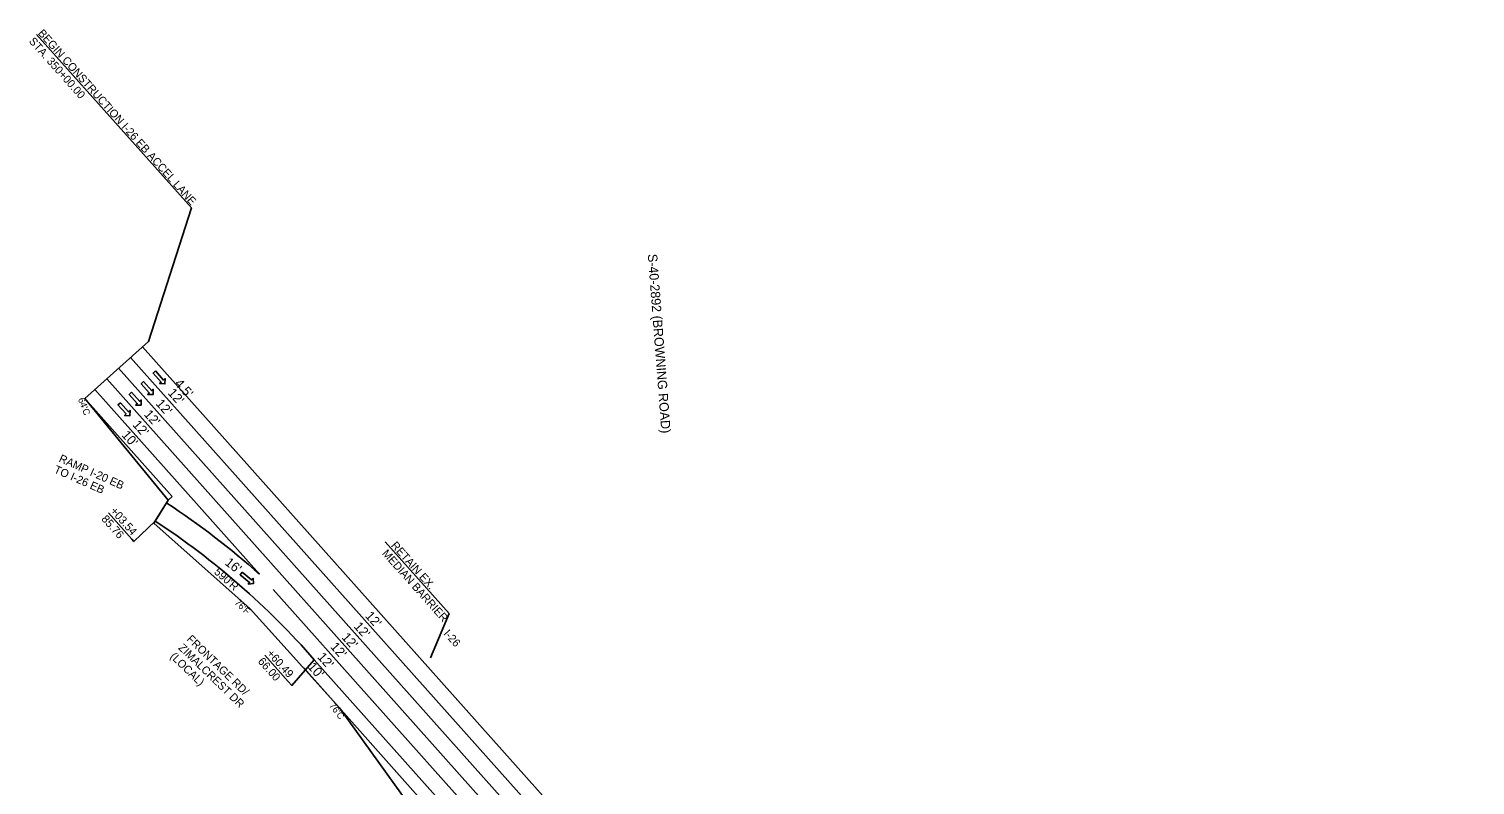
# Model space of a CAD drawing. Extents: x 1966090 to 1975830, y 788086 to 801233.
# Drawn here: x 1967014 to 1968098, y 800666 to 801233 of the extents above; entities that cross this region are included whole.
import ezdxf

# ---------------------------------------------------------------- set-up
doc = ezdxf.new("R2010")
doc.units = 0
for name, color, linetype in [('BR_PROPOSED_DRAINAGE', 7, 'Continuous'), ('RD_EX_Driveway_txCode', 7, 'Continuous'), ('RD_EX_RW_TX', 7, 'Continuous'), ('RD_EX_SU_Gas', 7, 'Continuous'), ('RD_EX_SU_H2O', 7, 'Continuous'), ('RD_PD_PaveShd', 7, 'Continuous'), ('RD_Sketch6', 7, 'Continuous'), ('RD_Sketch8', 7, 'Continuous')]:
    doc.layers.add(name, color=color, linetype=linetype)

msp = doc.modelspace()

# ---------------------------------------------------------------- linework, layer by layer
at = {"layer": 'BR_PROPOSED_DRAINAGE'}
for p, q in [((1967107.2, 800862.5), (1967179.5, 800798.4)), ((1967179.5, 800798.4), (1967246.3, 800724.1)), ((1967246.3, 800724.1), (1967305, 800642.4))]:
    msp.add_line(p, q, dxfattribs=at)
msp.add_lwpolyline([(1967055.5, 800955.8), (1967118, 800879.8), (1967107.2, 800862.5)], dxfattribs=at)
at = {"layer": 'RD_EX_Driveway_txCode'}
for points in [[(1967108.4, 800976.5), (1967106.6, 800974.9), (1967112.7, 800968.1), (1967111.5, 800967), (1967115.5, 800966.8), (1967115.8, 800970.8), (1967114.5, 800969.7)], [(1967099.5, 800968.5), (1967097.7, 800966.9), (1967103.8, 800960.1), (1967102.6, 800959), (1967106.6, 800958.8), (1967106.8, 800962.8), (1967105.6, 800961.7)], [(1967082.1, 800952.7), (1967080.3, 800951.1), (1967086.4, 800944.3), (1967085.2, 800943.2), (1967089.2, 800943), (1967089.4, 800947), (1967088.2, 800945.9)], [(1967090.5, 800960.5), (1967088.7, 800958.9), (1967094.8, 800952.1), (1967093.6, 800951), (1967097.6, 800950.8), (1967097.8, 800954.8), (1967096.6, 800953.7)], [(1967173.4, 800825.7), (1967171.9, 800823.9), (1967179, 800818.1), (1967178, 800816.8), (1967182, 800817.3), (1967181.6, 800821.2), (1967180.5, 800820)]]:
    msp.add_lwpolyline(points, close=True, dxfattribs=at)
at = {"layer": 'RD_EX_SU_Gas'}
for p, q in [((1967089.8, 800986.5), (1968088.8, 799867.6)), ((1967080.8, 800978.5), (1968079.9, 799859.6)), ((1967071.9, 800970.5), (1968070.9, 799851.6)), ((1967196.7, 800812.7), (1967576.5, 800387.3))]:
    msp.add_line(p, q, dxfattribs=at)
at = {"layer": 'RD_PD_PaveShd'}
for p, q in [((1967055.5, 800955.8), (1967121, 800882.5)), ((1967121, 800882.5), (1967118, 800879.8)), ((1967219.6, 800754), (1967753, 800156.6))]:
    msp.add_line(p, q, dxfattribs=at)
at = {"layer": 'RD_Sketch6'}
for p, q in [((1967090.7, 800850.6), (1967073.1, 800870.3)), ((1967280.6, 800848.6), (1967328.6, 800794.8)), ((1967328.6, 800794.8), (1967314.7, 800761.5)), ((1967208, 800744), (1967190.4, 800763.6))]:
    msp.add_line(p, q, dxfattribs=at)
for points in [[(1967103.2, 800998.5), (1967135.4, 801098.6), (1967019.2, 801228.6)], [(1967090.7, 800850.6), (1967092.3, 800848.7), (1967108.2, 800864.1)], [(1967208, 800744), (1967210.7, 800741), (1967227.5, 800760.2)]]:
    msp.add_lwpolyline(points, dxfattribs=at)
at = {"layer": 'RD_Sketch8'}
for p, q in [((1967103.2, 800998.5), (1967055.5, 800955.8)), ((1967098.7, 800994.5), (1968097.8, 799875.6)), ((1967062.9, 800962.5), (1967186.3, 800824.3)), ((1967108.2, 800864.1), (1967118, 800879.8)), ((1967227.5, 800760.2), (1967760.3, 800163.5))]:
    msp.add_line(p, q, dxfattribs=at)
for radius, start in [(606, 48.368), (590, 41.2312)]:
    msp.add_arc((1966783.8, 800371.3), radius, start, 56.6399, dxfattribs=at)

# ---------------------------------------------------------------- texts
at = {"layer": 'RD_EX_Driveway_txCode'}
for s, rotation, p in [('S-40-2892 (BROWNING ROAD)', 274.3864, (1967477.5, 801063.9)), ("12'", 311.7573, (1967117.2, 800959.7)), ("4.5'", 311.7573, (1967122.3, 800966.8)), ("12'", 311.7573, (1967108.2, 800951.7)), ("12'", 311.7573, (1967099.3, 800943.7)), ("10'", 311.7589, (1967082.6, 800928.2)), ("12'", 311.7573, (1967090.8, 800935.9)), ("16'", 321.7745, (1967159.9, 800831.9)), ("12'", 311.7605, (1967256.7, 800784.8)), ("12'", 311.7605, (1967265.2, 800792.7)), ("12'", 311.7605, (1967247.5, 800776.7)), ("12'", 311.7605, (1967239.1, 800769.6)), ("10'", 311.7605, (1967222.1, 800754.6)), ("12'", 311.7605, (1967229.4, 800761.9))]:
    msp.add_text(s, height=7, rotation=rotation, dxfattribs=at).set_placement(p)
at = {"layer": 'RD_EX_RW_TX'}
for s, rotation, p in [("64'C", 291.2562, (1967050.2, 800955.4)), ("76'F", 316.8565, (1967167.3, 800802.4)), ("76'C", 307.6061, (1967238.3, 800725.7))]:
    msp.add_text(s, height=5, rotation=rotation, dxfattribs=at).set_placement(p)
at = {"layer": 'RD_EX_SU_H2O'}
for s, rotation, p in [('RAMP I-20 EB ', 336.0256, (1967035.5, 800908.8)), ('TO I-26 EB', 336.0256, (1967031.8, 800900.6)), ('FRONTAGE RD/', 315.9539, (1967131.4, 800775.1)), ('ZIMALCREST DR', 315.9539, (1967125.1, 800768.6)), ('(LOCAL)', 315.9539, (1967118.9, 800762.1))]:
    msp.add_text(s, height=6, rotation=rotation, dxfattribs=at).set_placement(p)
at = {"layer": 'RD_Sketch6'}
for s, rotation, p in [('BEGIN CONSTRUCTION I-26 EB ACCEL LANE', 311.7606, (1967019.9, 801229.2)), ('STA. 350+00.00', 311.7606, (1967013.1, 801223.2)), ('85.76', 311.7605, (1967067.5, 800865.3)), ('+03.54', 311.7605, (1967074.2, 800871.3)), ('MEDIAN BARRIER', 311.7606, (1967277.9, 800839.5)), ('RETAIN EX. ', 311.7606, (1967284.6, 800845.5)), ("590'R", 318.735, (1967151.9, 800825.2)), ('I-26', 311.7606, (1967324, 800779.5)), ('+60.49', 311.7605, (1967191.5, 800764.6)), ('66.00', 311.7605, (1967184.8, 800758.6))]:
    msp.add_text(s, height=6, rotation=rotation, dxfattribs=at).set_placement(p)

doc.saveas('drawing.dxf')
